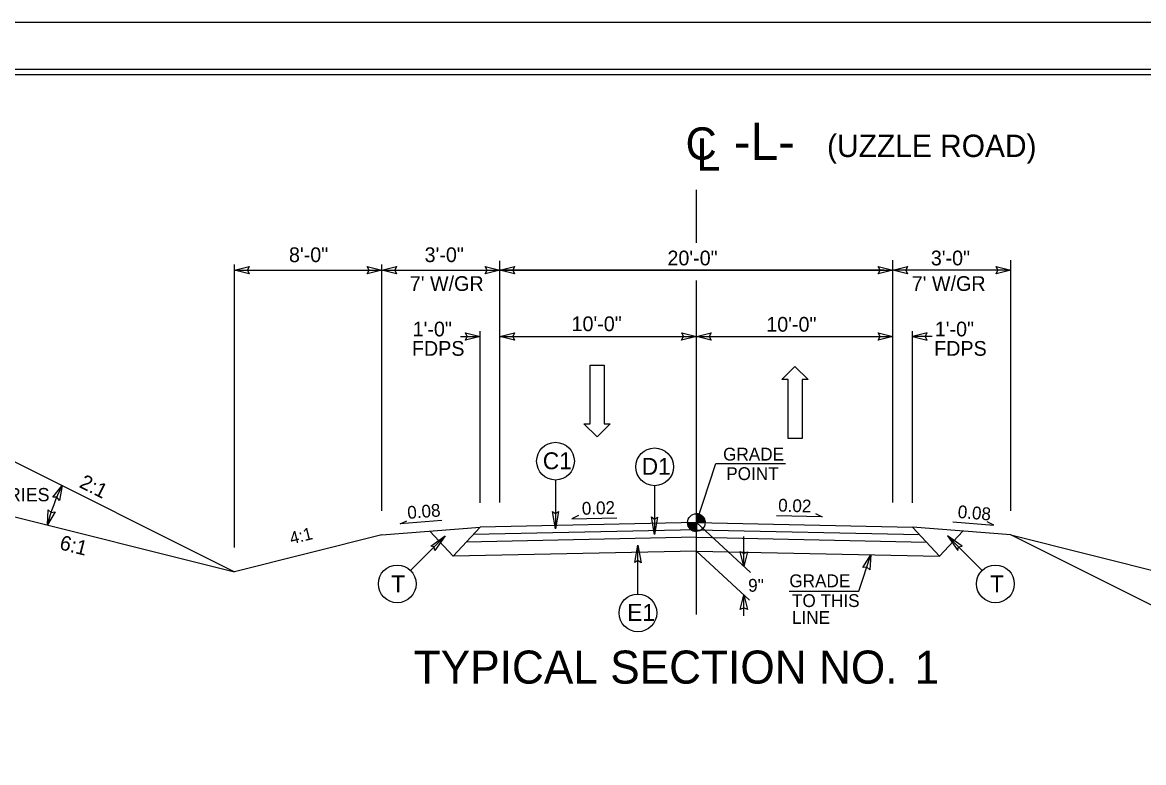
# Model space of a CAD drawing. Extents: x 574067 to 574470, y -53282 to -53062.
# Drawn here: x 574197 to 574304, y -53132.8 to -53062.1 of the extents above; entities that cross this region are included whole.
import ezdxf

# ---------------------------------------------------------------- set-up
doc = ezdxf.new("R2010")
doc.units = 0
for name, color, linetype in [('Old_Level_1', 7, 'Continuous'), ('Old_Level_11', 7, 'Continuous'), ('Old_Level_2', 7, 'Continuous'), ('Old_Level_3', 7, 'Continuous'), ('Prop Dimension', 7, 'Continuous'), ('Prop Dimension Text', 7, 'Continuous'), ('Prop Lane Arrow CELL', 7, 'Continuous'), ('Sheet Cutting Line CELL', 7, 'Continuous'), ('Sheet Plot Border Inside CELL', 7, 'Continuous'), ('Sheet Plot Border Outside CELL', 7, 'Continuous'), ('Sheet Typical CELL', 7, 'Continuous'), ('Typical Berm CELL', 7, 'Continuous'), ('Typical Berm Information CELL', 7, 'Continuous'), ('Typical Grade Point Symbol CELL', 7, 'Continuous'), ('Typical ID Circle CELL', 7, 'Continuous'), ('Typical Pavement Slope CELL', 7, 'Continuous'), ('Typical Slope Point Local CELL', 7, 'Continuous'), ('Typical Terminator CELL', 7, 'Continuous'), ('Typical Text Centerline CELL', 7, 'Continuous'), ('Typical Text General CELL', 7, 'Continuous'), ('Typical Text Grade Point CELL', 7, 'Continuous'), ('Typical Text ID Circle CELL', 7, 'Continuous')]:
    doc.layers.add(name, color=color, linetype=linetype)

# ---------------------------------------------------------------- blocks, each defined once
blk = doc.blocks.new('TERMINATOR')
at = {"layer": 'Typical Terminator CELL'}
blk.add_lwpolyline([(-0.469, 0.081), (0, 0), (-0.471, -0.083), (-0.411, 0)], close=True, dxfattribs=at)

msp = doc.modelspace()

# ---------------------------------------------------------------- linework, layer by layer
at = {"layer": 'Old_Level_2'}
for p, q in [((574261.35, -53083.16), (574261.35, -53078.11)), ((574261.35, -53118.64), (574261.35, -53086.75))]:
    msp.add_line(p, q, dxfattribs=at)
at = {"layer": 'Prop Dimension'}
for p, q in [((574291.35, -53085.76), (574280.1, -53085.76)), ((574238.85, -53092.11), (574240.72, -53092.11)), ((574283.85, -53092.11), (574281.97, -53092.11))]:
    msp.add_line(p, q, dxfattribs=at)
at = {"layer": 'Prop Dimension Text'}
for p, q in [((574242.6, -53107.95), (574242.6, -53084.87)), ((574280.1, -53107.95), (574280.1, -53084.83)), ((574291.35, -53108.73), (574291.35, -53084.83)), ((574217.29, -53112.25), (574217.29, -53085.23)), ((574217.29, -53085.76), (574280.1, -53085.76)), ((574231.35, -53108.73), (574231.35, -53085.23)), ((574279.26, -53085.76), (574242.6, -53085.76)), ((574240.72, -53107.98), (574240.72, -53091.58)), ((574242.6, -53092.11), (574280.1, -53092.11)), ((574281.97, -53107.98), (574281.97, -53091.58)), ((574261.35, -53109.86), (574266.51, -53114.63)), ((574265.87, -53114.04), (574265.87, -53111.19)), ((574261.35, -53112.59), (574266.41, -53117.26)), ((574265.87, -53118.75), (574265.87, -53116.76))]:
    msp.add_line(p, q, dxfattribs=at)
msp.add_arc((574217.29, -53114.55), 18.4, 153.4349, 165.9638, dxfattribs=at)
at = {"layer": 'Prop Lane Arrow CELL'}
for p, q in [((574251.22, -53100.43), (574251.22, -53094.83)), ((574251.22, -53094.83), (574252.54, -53094.83)), ((574252.54, -53094.83), (574252.54, -53100.43)), ((574269.51, -53096.22), (574270.75, -53094.96)), ((574270.75, -53094.96), (574272.03, -53096.22)), ((574270.11, -53096.22), (574269.51, -53096.22)), ((574270.11, -53101.82), (574270.11, -53096.22)), ((574272.03, -53096.22), (574271.43, -53096.22)), ((574271.43, -53096.22), (574271.43, -53101.82)), ((574251.9, -53101.69), (574250.62, -53100.43)), ((574250.62, -53100.43), (574251.22, -53100.43)), ((574253.14, -53100.43), (574251.9, -53101.69)), ((574252.54, -53100.43), (574253.14, -53100.43)), ((574271.43, -53101.82), (574270.11, -53101.82))]:
    msp.add_line(p, q, dxfattribs=at)
at = {"layer": 'Sheet Cutting Line CELL'}
msp.add_line((574403.73, -53062.12), (574066.93, -53062.12), dxfattribs=at)
at = {"layer": 'Sheet Plot Border Inside CELL'}
msp.add_lwpolyline([(574402.83, -53066.61), (574069.53, -53066.61), (574069.53, -53277.63), (574402.83, -53277.63)], close=True, dxfattribs=at)
at = {"layer": 'Sheet Plot Border Outside CELL'}
msp.add_lwpolyline([(574403.73, -53062.12), (574066.93, -53062.12), (574066.93, -53282.12), (574403.73, -53282.12)], close=True, dxfattribs=at)
at = {"layer": 'Sheet Typical CELL'}
msp.add_lwpolyline([(574400.33, -53067.12), (574100.33, -53067.12), (574100.33, -53277.12), (574400.33, -53277.12)], close=True, dxfattribs=at)
at = {"layer": 'Typical Berm CELL'}
for p, q in [((574238.14, -53113.08), (574235.91, -53110.67)), ((574238.14, -53113.08), (574240.72, -53110.29)), ((574261.35, -53110.56), (574240.06, -53111)), ((574261.35, -53109.86), (574240.72, -53110.29)), ((574261.35, -53109.86), (574281.97, -53110.29)), ((574261.35, -53110.56), (574282.63, -53111)), ((574284.55, -53113.07), (574281.97, -53110.29)), ((574284.55, -53113.07), (574286.78, -53110.67)), ((574261.35, -53111.26), (574239.4, -53111.72)), ((574261.35, -53111.26), (574283.3, -53111.72)), ((574261.35, -53112.59), (574238.14, -53113.08)), ((574261.35, -53112.59), (574284.55, -53113.07))]:
    msp.add_line(p, q, dxfattribs=at)
at = {"layer": 'Typical Berm Information CELL'}
for p, q in [((574250.09, -53109.18), (574249.48, -53109.49)), ((574249.48, -53109.49), (574253.76, -53109.4)), ((574273.34, -53109.3), (574269.01, -53109.21)), ((574272.73, -53108.99), (574273.34, -53109.3))]:
    msp.add_line(p, q, dxfattribs=at)
at = {"layer": 'Typical Grade Point Symbol CELL'}
for p, q in [((574261.35, -53109.86), (574263.22, -53104.23)), ((574261.35, -53109.86), (574261.35, -53109.02)), ((574260.51, -53109.86), (574261.35, -53109.86)), ((574262.19, -53109.86), (574261.35, -53109.86)), ((574261.35, -53110.7), (574261.35, -53109.86)), ((574261.35, -53109.86), (574261.35, -53110.7)), ((574276.85, -53116.41), (574278.01, -53112.94))]:
    msp.add_line(p, q, dxfattribs=at)
for points in [[(574261.35, -53109.02), (574261.35, -53109.02), (574261.35, -53109.86)], [(574261.37, -53109.02), (574261.37, -53109.86)], [(574261.39, -53109.02), (574261.39, -53109.86)], [(574261.41, -53109.02), (574261.41, -53109.86)], [(574261.42, -53109.02), (574261.42, -53109.86)], [(574261.44, -53109.03), (574261.44, -53109.86)], [(574261.46, -53109.03), (574261.46, -53109.86)], [(574261.47, -53109.03), (574261.47, -53109.86)], [(574261.49, -53109.03), (574261.49, -53109.86)], [(574261.51, -53109.03), (574261.51, -53109.86)], [(574261.52, -53109.04), (574261.52, -53109.86)], [(574261.54, -53109.04), (574261.54, -53109.86)], [(574261.56, -53109.05), (574261.56, -53109.86)], [(574261.57, -53109.05), (574261.57, -53109.86)], [(574261.59, -53109.06), (574261.59, -53109.86)], [(574261.61, -53109.06), (574261.61, -53109.86)], [(574261.62, -53109.07), (574261.62, -53109.86)], [(574261.64, -53109.07), (574261.64, -53109.86)], [(574261.66, -53109.08), (574261.66, -53109.86)], [(574261.67, -53109.09), (574261.67, -53109.86)], [(574261.69, -53109.09), (574261.69, -53109.86)], [(574261.71, -53109.1), (574261.71, -53109.86)], [(574261.72, -53109.11), (574261.72, -53109.86)], [(574261.74, -53109.12), (574261.74, -53109.86)], [(574261.76, -53109.13), (574261.76, -53109.86)], [(574261.77, -53109.14), (574261.77, -53109.86)], [(574261.79, -53109.15), (574261.79, -53109.86)], [(574261.81, -53109.16), (574261.81, -53109.86)], [(574261.82, -53109.17), (574261.82, -53109.86)], [(574261.84, -53109.18), (574261.84, -53109.86)], [(574261.86, -53109.19), (574261.86, -53109.86)], [(574261.88, -53109.21), (574261.88, -53109.86)], [(574261.89, -53109.22), (574261.89, -53109.86)], [(574261.91, -53109.24), (574261.91, -53109.86)], [(574261.93, -53109.25), (574261.93, -53109.86)], [(574261.94, -53109.27), (574261.94, -53109.86)], [(574261.96, -53109.28), (574261.96, -53109.86)], [(574261.98, -53109.3), (574261.98, -53109.86)], [(574261.99, -53109.32), (574261.99, -53109.86)], [(574262.01, -53109.34), (574262.01, -53109.86)], [(574262.03, -53109.37), (574262.03, -53109.86)], [(574262.04, -53109.39), (574262.04, -53109.86)], [(574262.06, -53109.42), (574262.06, -53109.86)], [(574262.08, -53109.45), (574262.08, -53109.86)], [(574262.09, -53109.47), (574262.09, -53109.86)], [(574262.11, -53109.51), (574262.11, -53109.86)], [(574262.13, -53109.55), (574262.13, -53109.86)], [(574262.14, -53109.6), (574262.14, -53109.86)], [(574262.16, -53109.65), (574262.16, -53109.86)], [(574260.51, -53109.86), (574260.51, -53109.95)], [(574260.53, -53109.86), (574260.53, -53110.05)], [(574260.55, -53109.86), (574260.55, -53110.11)], [(574260.56, -53109.86), (574260.56, -53110.16)], [(574260.58, -53109.86), (574260.58, -53110.2)], [(574260.6, -53109.86), (574260.6, -53110.23)], [(574260.61, -53109.86), (574260.61, -53110.27)], [(574260.63, -53109.86), (574260.63, -53110.3)], [(574260.65, -53109.86), (574260.65, -53110.32)], [(574260.66, -53109.86), (574260.66, -53110.35)], [(574260.68, -53109.86), (574260.68, -53110.37)], [(574260.7, -53109.86), (574260.7, -53110.39)], [(574260.71, -53109.86), (574260.71, -53110.41)], [(574260.73, -53109.86), (574260.73, -53110.43)], [(574260.75, -53109.86), (574260.75, -53110.45)], [(574260.76, -53109.86), (574260.76, -53110.46)], [(574260.78, -53109.86), (574260.78, -53110.48)], [(574260.8, -53109.86), (574260.8, -53110.49)], [(574260.81, -53109.86), (574260.81, -53110.51)], [(574260.83, -53109.86), (574260.83, -53110.52)], [(574260.85, -53109.86), (574260.85, -53110.53)], [(574260.86, -53109.86), (574260.86, -53110.55)], [(574260.88, -53109.86), (574260.88, -53110.56)], [(574260.9, -53109.86), (574260.9, -53110.57)], [(574260.91, -53109.86), (574260.91, -53110.58)], [(574260.93, -53109.86), (574260.93, -53110.59)], [(574260.95, -53109.86), (574260.95, -53110.6)], [(574260.97, -53109.86), (574260.97, -53110.61)], [(574260.98, -53109.86), (574260.98, -53110.61)], [(574261, -53109.86), (574261, -53110.62)], [(574261.02, -53109.86), (574261.02, -53110.63)], [(574261.03, -53109.86), (574261.03, -53110.64)], [(574261.05, -53109.86), (574261.05, -53110.64)], [(574261.07, -53109.86), (574261.07, -53110.65)], [(574261.08, -53109.86), (574261.08, -53110.66)], [(574261.1, -53109.86), (574261.1, -53110.66)], [(574261.12, -53109.86), (574261.12, -53110.66)], [(574261.13, -53109.86), (574261.13, -53110.67)], [(574261.15, -53109.86), (574261.15, -53110.67)], [(574261.17, -53109.86), (574261.17, -53110.68)], [(574261.18, -53109.86), (574261.18, -53110.68)], [(574261.2, -53109.86), (574261.2, -53110.69)], [(574261.22, -53109.86), (574261.22, -53110.69)], [(574261.23, -53109.86), (574261.23, -53110.69)], [(574261.25, -53109.86), (574261.25, -53110.69)], [(574261.27, -53109.86), (574261.27, -53110.69)], [(574261.28, -53109.86), (574261.28, -53110.7)], [(574261.3, -53109.86), (574261.3, -53110.7)], [(574261.32, -53109.86), (574261.32, -53110.7)], [(574261.33, -53109.86), (574261.33, -53110.7), (574261.33, -53110.7)], [(574262.18, -53109.74), (574262.18, -53109.86)]]:
    msp.add_lwpolyline(points, dxfattribs=at)
msp.add_circle((574261.35, -53109.86), 0.839, dxfattribs=at)
for start, end in [(359.9905, 89.9905), (179.9905, 269.9905)]:
    msp.add_arc((574261.35, -53109.86), 0.839, start, end, dxfattribs=at)
at = {"layer": 'Typical ID Circle CELL'}
for p, q in [((574247.91, -53105.81), (574247.91, -53110.47)), ((574257.37, -53106.34), (574257.37, -53111)), ((574234.08, -53114.43), (574237.38, -53111.14)), ((574288.61, -53114.43), (574285.31, -53111.14)), ((574255.77, -53116.67), (574255.77, -53112.01))]:
    msp.add_line(p, q, dxfattribs=at)
for centre in [(574247.91, -53104), (574257.37, -53104.54), (574232.81, -53115.71), (574289.88, -53115.71), (574255.77, -53118.48)]:
    msp.add_circle(centre, 1.8, dxfattribs=at)
at = {"layer": 'Typical Pavement Slope CELL'}
for p, q in [((574237.06, -53109.67), (574233.1, -53109.99)), ((574233.1, -53109.99), (574233.73, -53109.68)), ((574285.81, -53109.79), (574289.72, -53110.1)), ((574289.72, -53110.1), (574289.09, -53109.79))]:
    msp.add_line(p, q, dxfattribs=at)
at = {"layer": 'Typical Slope Point Local CELL'}
for p, q in [((574191.76, -53101.79), (574217.29, -53114.55)), ((574189.8, -53107.68), (574217.29, -53114.55)), ((574231.35, -53111.04), (574240.72, -53110.29)), ((574291.35, -53111.04), (574281.97, -53110.29)), ((574231.35, -53111.04), (574217.29, -53114.55)), ((574291.35, -53111.04), (574335.26, -53122.02)), ((574332.3, -53131.52), (574291.35, -53111.04))]:
    msp.add_line(p, q, dxfattribs=at)
at = {"layer": 'Typical Terminator CELL'}
for points in [[(574248.2, -53108.8), (574247.91, -53110.47), (574247.61, -53108.79), (574247.91, -53109)], [(574257.65, -53109.33), (574257.37, -53111), (574257.07, -53109.32), (574257.37, -53109.54)], [(574236, -53112.11), (574237.38, -53111.14), (574236.4, -53112.53), (574236.34, -53112.17)], [(574286.7, -53112.11), (574285.31, -53111.14), (574286.29, -53112.53), (574286.35, -53112.17)], [(574255.49, -53113.68), (574255.77, -53112.01), (574256.07, -53113.69), (574255.77, -53113.48)]]:
    msp.add_lwpolyline(points, close=True, dxfattribs=at)
at = {"layer": 'Typical Text Grade Point CELL'}
for p, q in [((574263.22, -53104.23), (574269.86, -53104.23)), ((574270.22, -53116.41), (574276.85, -53116.41))]:
    msp.add_line(p, q, dxfattribs=at)

# ---------------------------------------------------------------- block references
at = {"layer": 'Old_Level_11'}
for p, xscale, yscale, rotation in [((574217.29, -53085.76), 2.9825026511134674, 4.280821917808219, 180), ((574231.35, -53085.76), 2.9825026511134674, 4.280821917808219, 180), ((574242.6, -53085.76), 2.9825026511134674, 4.280821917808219, 180), ((574280.1, -53085.76), 2.9825026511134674, 4.280821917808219, 180), ((574242.6, -53092.11), 2.9825026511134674, 4.280821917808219, 180), ((574261.35, -53092.11), 2.9825026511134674, 4.280821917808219, 180), ((574281.97, -53092.11), 2.9825026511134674, -4.280821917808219, -180), ((574200.84, -53106.32), 2.9825026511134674, 4.28082191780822, 65.2036293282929), ((574199.45, -53110.09), 2.9825026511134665, 4.280821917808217, -106.02476566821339), ((574265.87, -53114.04), 2.9825026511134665, 4.280821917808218, -90.00000000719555), ((574278.01, -53112.94), 2.982502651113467, 4.280821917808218, 71.56505117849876), ((574265.87, -53116.76), 2.9825026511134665, 4.280821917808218, 90.00000000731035)]:
    msp.add_blockref('TERMINATOR', p, dxfattribs=dict(at, xscale=xscale, yscale=yscale, rotation=rotation))
at = {"layer": 'Old_Level_11', "xscale": 2.9825026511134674, "yscale": 4.280821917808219}
for p in [(574231.35, -53085.76), (574242.6, -53085.76), (574280.1, -53085.76), (574291.35, -53085.76), (574240.72, -53092.11), (574261.35, -53092.11), (574280.1, -53092.11)]:
    msp.add_blockref('TERMINATOR', p, dxfattribs=at)

# ---------------------------------------------------------------- texts
at = {"layer": 'Old_Level_1'}
msp.add_text('VARIES', height=1.27, dxfattribs=at).set_placement((574193.4, -53107.83))
at = {"layer": 'Old_Level_11'}
msp.add_text('-L-', height=3.562, dxfattribs=at).set_placement((574264.92, -53075.26))
at = {"layer": 'Old_Level_3'}
for s, height, p in [('TYPICAL SECTION NO.  ', 3.1536, (574234.38, -53125.23)), ('1', 3.15, (574282.18, -53125.25))]:
    msp.add_text(s, height=height, dxfattribs=at).set_placement(p)
at = {"layer": 'Prop Dimension Text'}
for s, p in [('8\'-0"', (574222.48, -53085)), ('3\'-0"', (574235.42, -53085)), ('20\'-0"', (574258.59, -53085.31)), ('3\'-0"', (574283.72, -53085.31)), ("7' W/GR", (574234.01, -53087.75)), ("7' W/GR", (574281.9, -53087.75)), ('10\'-0"', (574249.44, -53091.59)), ('10\'-0"', (574268.02, -53091.64)), ('1\'-0"', (574234.28, -53092.09)), ('1\'-0"', (574284.1, -53092.09)), ('FDPS', (574234.21, -53093.94)), ('FDPS', (574284.04, -53093.94))]:
    msp.add_text(s, height=1.406, dxfattribs=at).set_placement(p)
msp.add_text('0.08 ', height=1.217, rotation=355.4261, dxfattribs=at).set_placement((574286.25, -53109.41))
at = {"layer": 'Typical Berm CELL'}
msp.add_text('0.08', height=1.217, rotation=4.5739, dxfattribs=at).set_placement((574233.82, -53109.52))
at = {"layer": 'Typical Berm Information CELL'}
for rotation, p in [(1.8084, (574250.44, -53109.12)), (358.1916, (574269.14, -53108.8))]:
    msp.add_text('0.02', height=1.217, rotation=rotation, dxfattribs=at).set_placement(p)
at = {"layer": 'Typical Slope Point Local CELL'}
msp.add_text('4:1', height=1.172, rotation=14.0362, dxfattribs=at).set_placement((574222.71, -53111.95))
at = {"layer": 'Typical Text Centerline CELL'}
msp.add_text('C', height=3.08, dxfattribs=at).set_placement((574260.32, -53075.22))
msp.add_text('L', height=3.08, rotation=359.9469, dxfattribs=at).set_placement((574261.35, -53076.27))
at = {"layer": 'Typical Text General CELL'}
msp.add_text('(UZZLE ROAD)', height=2.135, dxfattribs=at).set_placement((574273.82, -53074.97))
for s, rotation, p in [('2:1', 333.4349, (574202.38, -53106.45)), ('6:1', 345.7105, (574200.51, -53112.39))]:
    msp.add_text(s, height=1.399, rotation=rotation, dxfattribs=at).set_placement(p)
at = {"layer": 'Typical Text Grade Point CELL'}
for s, p in [('GRADE', (574263.9, -53103.94)), ('POINT', (574264.2, -53105.8)), ('GRADE', (574270.22, -53116.03)), ('9"', (574266.29, -53116.46)), ('TO THIS', (574270.47, -53117.92)), ('LINE', (574270.47, -53119.53))]:
    msp.add_text(s, height=1.223, dxfattribs=at).set_placement(p)
at = {"layer": 'Typical Text ID Circle CELL'}
for s, height, p in [('C1', 1.614, (574246.7, -53104.77)), ('D1', 1.614, (574256.14, -53105.3)), ('T', 1.61, (574232.24, -53116.52)), ('T', 1.61, (574289.37, -53116.52)), ('E1', 1.614, (574254.76, -53119.24))]:
    msp.add_text(s, height=height, dxfattribs=at).set_placement(p)

doc.saveas('drawing.dxf')
